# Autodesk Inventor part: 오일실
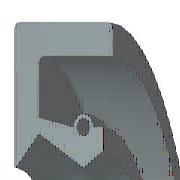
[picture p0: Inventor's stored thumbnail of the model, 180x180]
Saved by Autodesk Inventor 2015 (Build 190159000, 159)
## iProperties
Created: 2009-02
Part Number: 오일실
Material: 고무
Description: 오일-실
Document SubType Name: Modeling
Standard: KS B 2804
Designer: SeoGD™
Standards Organization: KS
Language: ko-KR
Size Designation: D - 10 20 7
Categories: <MemberInstance><Categories><Category DisplayName="샤프트 부품" InternalName="7f7aeb1f-a693-4053-b835-cee3144e0d98" Mnemonic="SHFT"><Category DisplayName="실링" Intern
Density: 0.93 g/cm^3
Appearance: 고무 - 검은색 - 버전 1.1
IsCustomPart: 0
Author: SeoGD™
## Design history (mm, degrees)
revolve "본체" stored, may be unused: angle "d17" = 90 deg
revolve "스프링1" stored, may be unused: angle "d18" = 90 deg
body "Solid1"
sketch "스케치1"
  geometry: L1 (0, 10)-(7, 10); L2 (7, 8.25)-(1.75, 8.25); L3 (1.75, 6.75)-(4.9, 5); L4 (4.9, 5)-(0, 5); L5 (0, 0)-(9.586, 0) reference; L6 (4.9, 5)-(6.3, 5.875); L7 (0, 18)-(0, -3) reference; L8 (-1.941, 0)-(11.507, 0) reference; L9 (4.2, 7.1)-(1.75, 7.59); L10 (1.75, 7.59)-(1.75, 8.25); L11 (0, 10)-(0, 5.088); L12 (4.9, 5)-(0, 5); L13 (1.75, 6.75)-(0.152, 5.028); L14 (7, 10)-(7, 8.25); L15 (5.6, 7.1)-(6.3, 7.1); L16 (6.3, 7.1)-(6.3, 5.875); C1 r 0.455 at (4.9, 7.1); A1 r 0.7 centre (4.9, 7.1) between (5.6, 7.1) and (4.2, 7.1); A2 r 0.088 centre (0.088, 5.088) between (0, 5.088) and (0.152, 5.028); 1 further point
  constraints: 28 end point, 5 horizontal alignment, 5 point on line, 4 point on circle, 4 vertical alignment, 3 centre point, 3 tangent, 2 collinear, 2 horizontal, 2 perpendicular, 1 coincident, 1 parallel
  dimensions: "d0" = 20 diameter of L1 L5 (= SD2); "d1" = 1.75 distance of L1.end L2.start (= SD); "d2" = 0.91 diameter of C1 (= SPDI); "d3" = 1.4 diameter of A1 (= SPDA); "d4" = 10 diameter of L3.end L5 (= NND); "d5" = 13.5 diameter of L3.start L5 (= TKDM); "d7" = 15.18 diameter of L9.end L5 (= TKDM + 0.24 x SWDT); "d8" = 1.75 distance between parallel lines of L11 L10 (= SD); "d9" = 4.9 distance from line of L11 C1.centre (= SPDST); "d10" = 14.2 diameter of C1.centre L5 (= HLDM); "d11" = 0.0875 radius of A2 (= 0.25 x LAB); "d12" = 6.3 distance between parallel lines of L11 L16 (= SDI); "d13" = 11.75 diameter of L6.end L5 (= ABDM); "d14" = 7 distance from line of L11 L1.end (= SWDT)
fillet "모깎기1" dims "d6" = 0.3 (= RR)
other parameters: "SD2" = 20 [user parameter; used in 1 equation term], "SWDT" = 7 [user parameter; used in 2 equation terms], "RR" = 0.3 [user parameter; used in 1 equation term], "SD" = 1.75 [user parameter; used in 2 equation terms], "NND" = 10 [user parameter; used in 1 equation term], "SPDA" = 1.4 [user parameter; used in 1 equation term], "SPDI" = 0.91 [user parameter; used in 1 equation term], "TKDM" = 13.5 [user parameter; used in 2 equation terms], "HLDM" = 14.2 [user parameter; used in 1 equation term], "ABDM" = 11.75 [user parameter; used in 1 equation term], "SDI" = 6.3 [user parameter; used in 1 equation term], "SPDST" = 4.9 [user parameter; used in 1 equation term], "LAB" = 0.35 [user parameter; used in 1 equation term], "d15" = 0, "d16" = 0, "d19" = 0
